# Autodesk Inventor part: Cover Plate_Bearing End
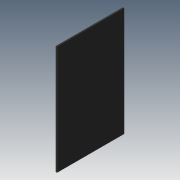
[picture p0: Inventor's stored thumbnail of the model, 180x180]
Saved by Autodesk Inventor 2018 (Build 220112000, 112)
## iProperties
Created: 2018-02
Part Number: Cover Plate_Bearing End
Material: Steel, Mild
Document SubType Name: Modeling
Designer: STK
Density: 7.85 g/cm^3
Appearance: Rubber - Black
Author: STK
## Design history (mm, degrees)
sketch "Sketch1"
  geometry: L1 (-320.675, 196.85)-(320.675, 196.85); L2 (320.675, 196.85)-(320.675, -196.85); L3 (320.675, -196.85)-(-320.675, -196.85); L4 (-320.675, -196.85)-(-320.675, 196.85); L5 (-320.675, 196.85)-(320.675, -196.85); L6 (320.675, 196.85)-(-320.675, -196.85); 1 further point
  constraints: 12 end point, 2 midpoint, 2 parallel, 1 horizontal, 1 perpendicular
  dimensions: "d0" = 641.35 distance of L2.end L3.end; "d1" = 393.7 distance of L1.end L2.end
extrude "Extrusion1" new body sketch "Sketch1" distance "d2" = 6.35; taper "d3" = 0 deg
body "Solid1"
